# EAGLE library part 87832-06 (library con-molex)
Milli-Grid Header 2.00mm (.079") Pitch
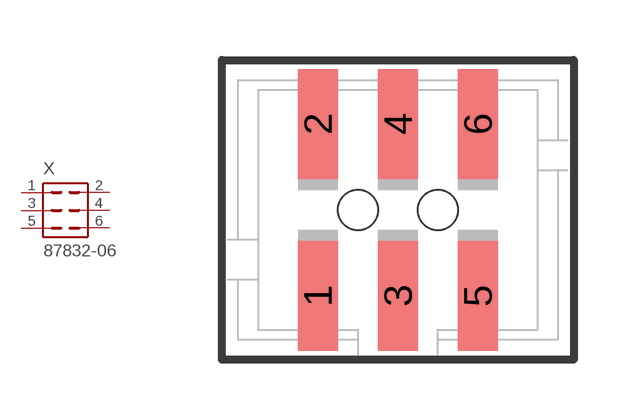
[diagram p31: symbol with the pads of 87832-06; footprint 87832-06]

Designator prefix X

## 87832-06 (OC_FARNELL: 1756947; OC_NEWARK: unknown)  [87832-06]
1  1  pas
2  2  pas
3  3  pas
4  4  pas
5  5  pas
6  6  pas

## Footprint 87832-06 (pad centres in mm)
PCB Headers 2.00mm (.079") Pitch Milli-Grid Header, Vertical, Shrouded
smd 1 x 2.75: 1 -2,-2.15; 2 -2,2.15; 3 0,-2.15; 4 0,2.15; 5 2,-2.15; 6 2,2.15
hole 1 at -1,0
hole 1 at 1,0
